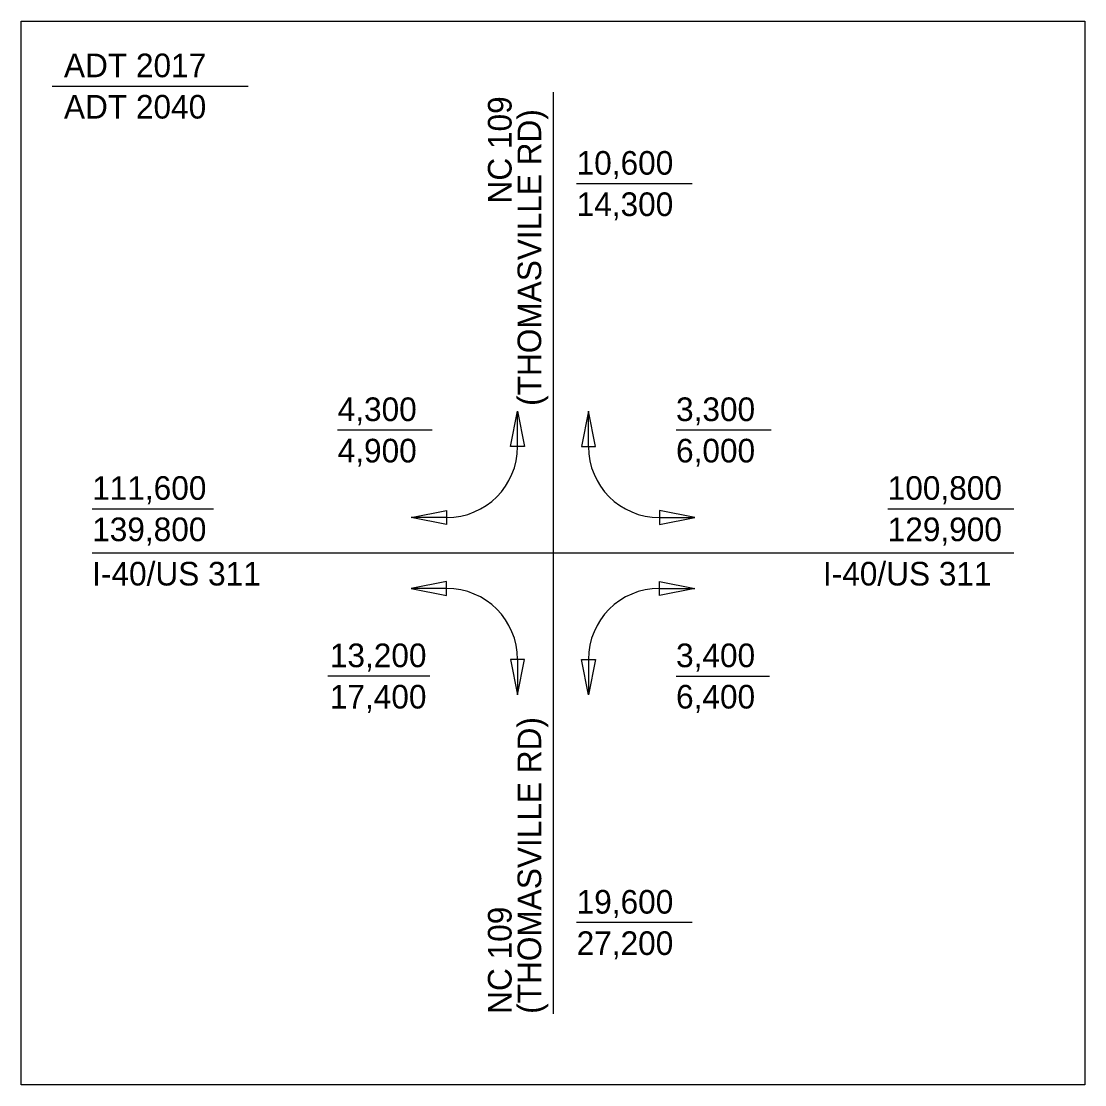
# Model space of a CAD drawing. Extents: x 1639431 to 1642602, y 841916 to 843940.
# Drawn here: x 1642376.8 to 1642601.8, y 842693.7 to 842918.7 of the extents above; entities that cross this region are included whole.
import ezdxf

# ---------------------------------------------------------------- set-up
doc = ezdxf.new("R2010")
doc.units = 0
doc.layers.add('Default', color=7, linetype='Continuous')

msp = doc.modelspace()

# ---------------------------------------------------------------- linework, layer by layer
at = {"layer": 'Default'}
for p, q in [((1642383.38, 842904.97), (1642424.84, 842904.97)), ((1642489.35, 842903.69), (1642489.35, 842708.69)), ((1642494.35, 842884.36), (1642518.76, 842884.36)), ((1642481.85, 842828.69), (1642481.85, 842836.19)), ((1642496.85, 842828.69), (1642496.85, 842836.19)), ((1642443.79, 842832.22), (1642463.79, 842832.22)), ((1642515.38, 842832.22), (1642535.54, 842832.22)), ((1642391.85, 842815.56), (1642417.52, 842815.56)), ((1642560.16, 842815.56), (1642586.85, 842815.56)), ((1642466.85, 842813.69), (1642459.35, 842813.69)), ((1642511.85, 842813.69), (1642519.35, 842813.69)), ((1642391.85, 842806.19), (1642586.85, 842806.19)), ((1642466.85, 842798.69), (1642459.35, 842798.69)), ((1642511.85, 842798.69), (1642519.35, 842798.69)), ((1642481.85, 842783.69), (1642481.85, 842776.19)), ((1642496.85, 842783.69), (1642496.85, 842776.19)), ((1642463.31, 842780.15), (1642441.74, 842780.15)), ((1642515.38, 842780.15), (1642535.15, 842780.15)), ((1642518.76, 842728.02), (1642494.35, 842728.02))]:
    msp.add_line(p, q, dxfattribs=at)
for points in [[(1642376.85, 842693.69), (1642376.85, 842918.69), (1642601.85, 842918.69), (1642601.85, 842693.69)], [(1642481.85, 842836.19), (1642483.35, 842828.69), (1642480.35, 842828.69)], [(1642496.85, 842836.19), (1642495.35, 842828.69), (1642498.35, 842828.69)], [(1642459.35, 842813.69), (1642466.85, 842815.19), (1642466.85, 842812.19)], [(1642519.35, 842813.69), (1642511.85, 842815.19), (1642511.85, 842812.19)], [(1642459.35, 842798.69), (1642466.85, 842797.19), (1642466.85, 842800.19)], [(1642519.35, 842798.69), (1642511.85, 842797.19), (1642511.85, 842800.19)], [(1642481.85, 842776.19), (1642483.35, 842783.69), (1642480.35, 842783.69)], [(1642496.85, 842776.19), (1642495.35, 842783.69), (1642498.35, 842783.69)]]:
    msp.add_lwpolyline(points, close=True, dxfattribs=at)
for centre, start, end in [((1642466.85, 842828.69), 270, 360), ((1642511.85, 842828.69), 180, 270), ((1642466.85, 842783.69), 360, 90), ((1642511.85, 842783.69), 90, 180)]:
    msp.add_arc(centre, 15, start, end, dxfattribs=at)

# ---------------------------------------------------------------- texts
for s, rotation, p in [('ADT 2017', 360, (1642385.88, 842906.85)), ('ADT 2040', 360, (1642385.88, 842898.1)), ('NC 109', 90, (1642480.59, 842880.14)), ('(THOMASVILLE RD)', 90, (1642486.85, 842837.31)), ('10,600', 360, (1642494.35, 842886.23)), ('14,300', 360, (1642494.35, 842877.48)), ('4,300', 360, (1642443.79, 842834.1)), ('3,300', 360, (1642515.38, 842834.1)), ('4,900', 360, (1642443.79, 842825.35)), ('6,000', 360, (1642515.38, 842825.35)), ('111,600', 360, (1642391.85, 842817.44)), ('100,800', 360, (1642560.16, 842817.44)), ('139,800', 360, (1642391.85, 842808.69)), ('129,900', 360, (1642560.16, 842808.69)), ('I-40/US 311', 360, (1642391.85, 842799.31)), ('I-40/US 311', 360, (1642546.46, 842799.31)), ('13,200', 360, (1642442.13, 842782.03)), ('3,400', 360, (1642515.38, 842782.03)), ('17,400', 360, (1642442.13, 842773.28)), ('6,400', 360, (1642515.38, 842773.28)), ('(THOMASVILLE RD)', 90, (1642486.85, 842708.69)), ('19,600', 360, (1642494.35, 842729.89)), ('NC 109', 90, (1642480.59, 842708.69)), ('27,200', 360, (1642494.35, 842721.14))]:
    msp.add_text(s, height=5, rotation=rotation, dxfattribs=at).set_placement(p)

doc.saveas('drawing.dxf')
